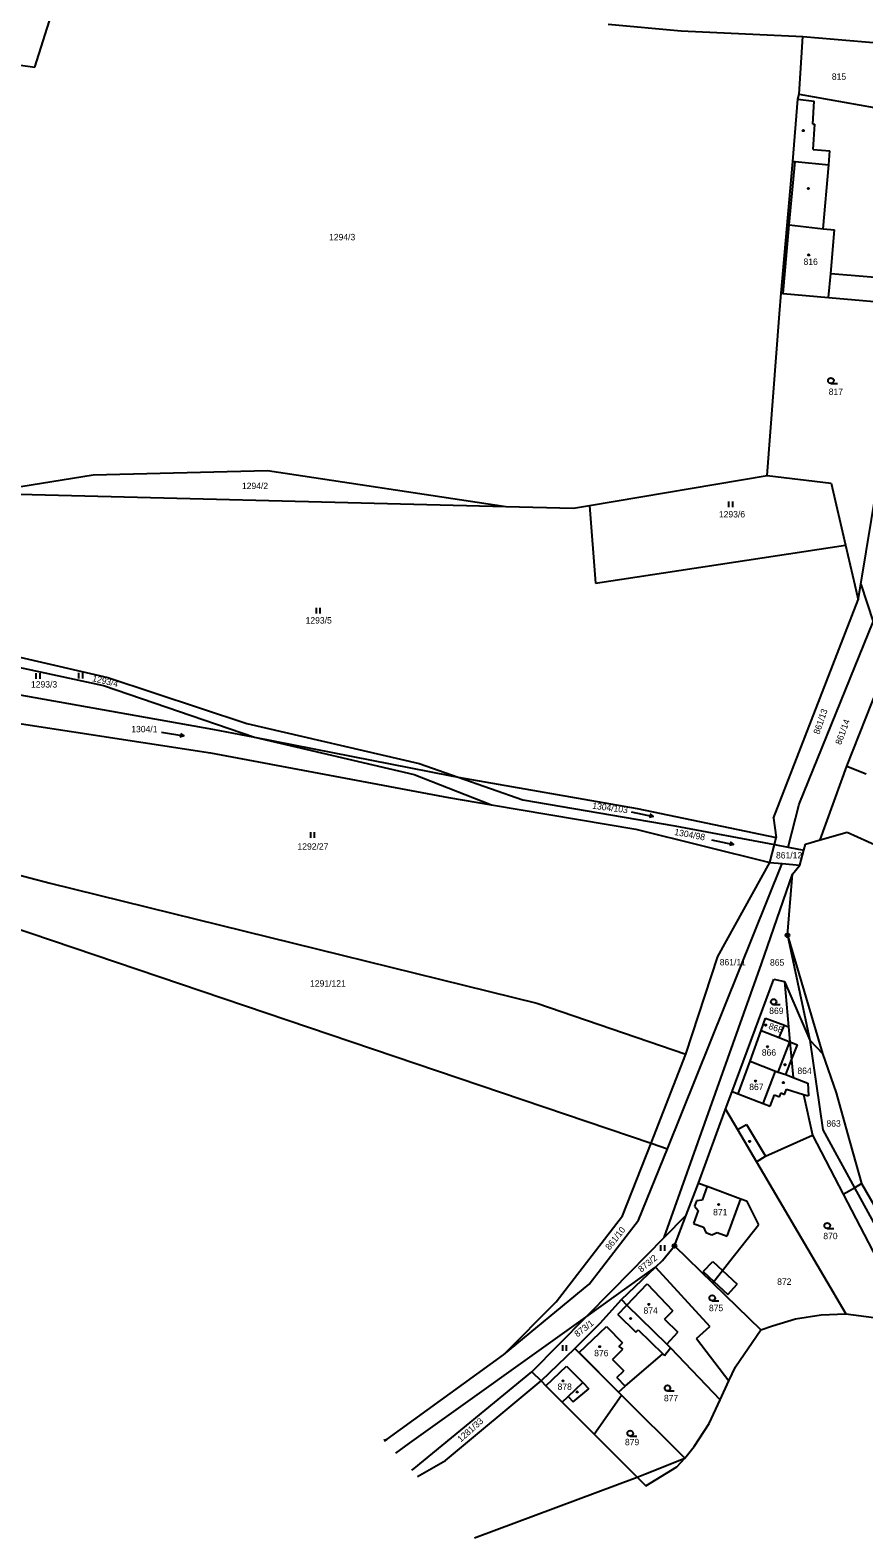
# Model space of a CAD drawing. Extents: x -779596 to -776743, y -1030330 to -1024513.
# Drawn here: x -778014.2 to -777792.7, y -1025697.8 to -1025297.1 of the extents above; entities that cross this region are included whole.
import ezdxf

# ---------------------------------------------------------------- set-up
doc = ezdxf.new("R2010")
doc.units = 0
for name, color, linetype in [('hranice parcel', 7, 'Continuous'), ('hranice vnitřní', 7, 'Continuous'), ('kultura', 7, 'Continuous'), ('Kód', 7, 'Continuous'), ('č_pacel stav_', 7, 'Continuous'), ('č_parcel poz_', 7, 'Continuous')]:
    doc.layers.add(name, color=color, linetype=linetype)

msp = doc.modelspace()

# ---------------------------------------------------------------- linework, layer by layer
at = {"layer": 'hranice parcel'}
for points in [[(-778012.95, -1025306.97), (-778004.12, -1025278.91)], [(-777860.63, -1025295.52), (-777841.25, -1025297.36)], [(-777841.25, -1025297.36), (-777808.98, -1025298.81)], [(-777809.95, -1025314.14), (-777808.98, -1025298.81)], [(-777808.98, -1025298.81), (-777788.09, -1025300.64)], [(-778028.28, -1025304.88), (-778012.95, -1025306.97)], [(-777811.57, -1025332.03), (-777810.25, -1025315.48)], [(-777810.25, -1025315.48), (-777809.95, -1025314.14)], [(-777809.95, -1025314.14), (-777789.98, -1025317.73)], [(-777814.67, -1025367.05), (-777811.57, -1025332.03)], [(-777815.16, -1025372.54), (-777814.67, -1025367.05)], [(-777814.67, -1025367.05), (-777814.17, -1025367.09)], [(-777814.17, -1025367.09), (-777802.12, -1025368.16)], [(-777802.12, -1025368.16), (-777781.81, -1025369.97)], [(-777818.4, -1025415.44), (-777815.16, -1025372.54)], [(-778027.77, -1025420.18), (-777997.46, -1025415.31)], [(-777997.46, -1025415.31), (-777951.14, -1025414.16)], [(-777951.14, -1025414.16), (-777887.84, -1025423.69)], [(-777865.62, -1025423.43), (-777818.4, -1025415.44)], [(-777818.4, -1025415.44), (-777801.44, -1025417.56)], [(-778027.77, -1025420.18), (-777887.84, -1025423.69)], [(-777801.44, -1025417.56), (-777797.59, -1025434.03)], [(-777793.53, -1025444.4), (-777789.28, -1025418.59)], [(-777887.84, -1025423.69), (-777869.84, -1025424.14)], [(-777869.84, -1025424.14), (-777865.62, -1025423.43)], [(-777865.62, -1025423.43), (-777864.07, -1025444.05)], [(-777864.07, -1025444.05), (-777797.59, -1025434.03)], [(-777797.59, -1025434.03), (-777795.13, -1025444.58)], [(-777795.13, -1025444.58), (-777794.21, -1025448.52)], [(-777794.21, -1025448.52), (-777793.53, -1025444.4)], [(-777793.53, -1025444.4), (-777790.21, -1025454.41)], [(-777816.77, -1025506.5), (-777794.21, -1025448.52)], [(-777809.88, -1025502.83), (-777790.21, -1025454.41)], [(-778040.44, -1025458.35), (-777993.61, -1025469.18)], [(-778040.76, -1025461.34), (-777994.79, -1025471.25)], [(-777993.61, -1025469.18), (-777956.63, -1025481.4)], [(-778039.94, -1025469.72), (-777965.75, -1025482.86)], [(-777994.79, -1025471.25), (-777954.64, -1025485.05)], [(-777797.26, -1025492.75), (-777788.88, -1025471.44)], [(-778039.13, -1025478.05), (-777966.3, -1025489.21)], [(-777965.75, -1025482.86), (-777954.64, -1025485.05)], [(-777956.63, -1025481.4), (-777910.87, -1025492.03)], [(-777954.64, -1025485.05), (-777902.85, -1025495.24)], [(-777954.64, -1025485.05), (-777912.18, -1025494.91)], [(-777966.3, -1025489.21), (-777903.1, -1025501.05)], [(-777910.87, -1025492.03), (-777900.51, -1025495.65)], [(-777804.37, -1025512.26), (-777797.26, -1025492.75)], [(-777797.26, -1025492.75), (-777792.15, -1025494.76)], [(-777912.18, -1025494.91), (-777891.67, -1025502.98)], [(-777902.85, -1025495.24), (-777900.51, -1025495.65)], [(-777900.51, -1025495.65), (-777852.96, -1025504)], [(-777900.51, -1025495.65), (-777883.35, -1025501.65)], [(-777903.1, -1025501.05), (-777891.67, -1025502.98)], [(-777891.67, -1025502.98), (-777853.31, -1025509.46)], [(-777883.35, -1025501.65), (-777842.95, -1025508.56)], [(-777852.96, -1025504), (-777816.01, -1025511.63)], [(-777812.86, -1025514.21), (-777809.88, -1025502.83)], [(-777842.95, -1025508.56), (-777816.48, -1025513.53)], [(-777816.77, -1025506.5), (-777816.01, -1025511.63)], [(-777853.31, -1025509.46), (-777817.68, -1025518.32)], [(-777816.48, -1025513.53), (-777816.01, -1025511.63)], [(-777808.25, -1025513.45), (-777804.37, -1025512.26)], [(-777804.37, -1025512.26), (-777797.12, -1025510.29)], [(-777797.12, -1025510.29), (-777788.92, -1025513.97)], [(-778036.06, -1025516.7), (-778008.92, -1025523.8)], [(-777817.68, -1025518.32), (-777816.48, -1025513.53)], [(-777816.48, -1025513.53), (-777812.86, -1025514.21)], [(-777812.86, -1025514.21), (-777808.67, -1025515)], [(-777809.76, -1025519.05), (-777808.67, -1025515)], [(-777808.67, -1025515), (-777808.25, -1025513.45)], [(-777844.94, -1025594.37), (-777814.43, -1025518.62)], [(-777831.51, -1025543.32), (-777817.68, -1025518.32)], [(-777817.68, -1025518.32), (-777814.43, -1025518.62)], [(-777814.43, -1025518.62), (-777809.76, -1025519.05)], [(-777811.66, -1025521.39), (-777809.76, -1025519.05)], [(-778008.92, -1025523.8), (-777879.61, -1025555.7)], [(-777819.94, -1025545.22), (-777811.66, -1025521.39)], [(-777813.02, -1025537.66), (-777811.66, -1025521.39)], [(-778036.95, -1025529.43), (-777849.27, -1025592.9)], [(-777813.02, -1025537.66), (-777807.04, -1025565.5)], [(-777845.75, -1025617.95), (-777819.94, -1025545.22)], [(-777840.02, -1025569.28), (-777831.51, -1025543.32)], [(-777827.76, -1025579.16), (-777816.65, -1025549.3)], [(-777816.65, -1025549.3), (-777813.78, -1025549.91)], [(-777813.78, -1025549.91), (-777807.04, -1025565.5)], [(-777813.78, -1025549.91), (-777812.71, -1025561.94)], [(-777879.61, -1025555.7), (-777840.02, -1025569.28)], [(-777820.05, -1025562.97), (-777818.87, -1025559.71)], [(-777818.87, -1025559.71), (-777813.85, -1025561.52)], [(-777822.97, -1025571.07), (-777820.05, -1025562.97)], [(-777820.05, -1025562.97), (-777815.2, -1025564.86)], [(-777815.2, -1025564.86), (-777812.35, -1025565.97)], [(-777813.85, -1025561.52), (-777812.71, -1025561.94)], [(-777812.71, -1025561.94), (-777812.35, -1025565.97)], [(-777849.27, -1025592.9), (-777840.02, -1025569.28)], [(-777812.35, -1025565.97), (-777811.93, -1025570.74)], [(-777807.04, -1025565.5), (-777803.7, -1025569.05)], [(-777807.04, -1025565.5), (-777803.66, -1025589.38)], [(-777803.7, -1025569.05), (-777800.12, -1025579.56)], [(-777826.12, -1025579.79), (-777822.97, -1025571.07)], [(-777822.97, -1025571.07), (-777816.17, -1025573.72)], [(-777811.93, -1025570.74), (-777811.51, -1025575.46)], [(-777816.17, -1025573.72), (-777815.45, -1025574)], [(-777815.45, -1025574), (-777813.49, -1025574.69)], [(-777813.49, -1025574.69), (-777811.51, -1025575.46)], [(-777811.51, -1025575.46), (-777807.59, -1025576.98)], [(-777807.59, -1025576.98), (-777807.46, -1025580.31)], [(-777829.5, -1025583.86), (-777827.76, -1025579.16)], [(-777827.76, -1025579.16), (-777826.12, -1025579.79)], [(-777808.73, -1025579.93), (-777806.33, -1025590.77)], [(-777808.73, -1025579.93), (-777807.46, -1025580.31)], [(-777800.12, -1025579.56), (-777797.15, -1025590.05)], [(-777836.67, -1025603.51), (-777829.5, -1025583.86)], [(-777829.5, -1025583.86), (-777826.29, -1025589.3)], [(-777826.29, -1025589.3), (-777821.28, -1025597.82)], [(-777803.66, -1025589.38), (-777795.23, -1025604.74)], [(-777856.84, -1025612.23), (-777849.27, -1025592.9)], [(-777849.27, -1025592.9), (-777844.94, -1025594.37)], [(-777818.82, -1025596.37), (-777806.33, -1025590.77)], [(-777806.33, -1025590.77), (-777798.19, -1025606.43)], [(-777797.15, -1025590.05), (-777793.31, -1025603.64)], [(-777852.58, -1025613.33), (-777844.94, -1025594.37)], [(-777821.28, -1025597.82), (-777818.82, -1025596.37)], [(-777821.28, -1025597.82), (-777797.48, -1025638.2)], [(-777839.92, -1025612.03), (-777836.67, -1025603.51)], [(-777836.67, -1025603.51), (-777834.38, -1025604.35)], [(-777834.38, -1025604.35), (-777825.39, -1025607.66)], [(-777798.19, -1025606.43), (-777795.23, -1025604.74)], [(-777795.23, -1025604.74), (-777793.31, -1025603.64)], [(-777795.23, -1025604.74), (-777774.45, -1025642.57)], [(-777825.39, -1025607.66), (-777823.91, -1025608.21)], [(-777823.91, -1025608.21), (-777820.74, -1025614.57)], [(-777798.19, -1025606.43), (-777780.25, -1025640.96)], [(-777874.49, -1025635.07), (-777856.84, -1025612.23)], [(-777865.73, -1025630.39), (-777852.58, -1025613.33)], [(-777845.75, -1025617.95), (-777839.92, -1025612.03)], [(-777843.03, -1025620.17), (-777839.92, -1025612.03)], [(-777828.4, -1025624.36), (-777820.74, -1025614.57)], [(-777859.53, -1025631.94), (-777845.75, -1025617.95)], [(-777846.2, -1025624.06), (-777843.03, -1025620.17)], [(-777843.03, -1025620.17), (-777832.86, -1025630.06)], [(-777848.08, -1025625.84), (-777846.2, -1025624.06)], [(-777830.27, -1025626.75), (-777828.4, -1025624.36)], [(-777866.63, -1025639.13), (-777848.08, -1025625.84)], [(-777857.13, -1025634.46), (-777848.08, -1025625.84)], [(-777848.08, -1025625.84), (-777833.69, -1025641.63)], [(-777832.56, -1025629.67), (-777830.27, -1025626.75)], [(-777888.44, -1025649.11), (-777865.73, -1025630.39)], [(-777866.63, -1025639.13), (-777859.53, -1025631.94)], [(-777832.86, -1025630.06), (-777832.56, -1025629.67)], [(-777832.86, -1025630.06), (-777820.1, -1025642.48)], [(-777888.44, -1025649.11), (-777874.49, -1025635.07)], [(-777862.77, -1025640.73), (-777857.13, -1025634.46)], [(-777857.13, -1025634.46), (-777855.71, -1025635.95)], [(-777855.71, -1025635.95), (-777845.05, -1025646.28)], [(-777913.42, -1025672.65), (-777866.63, -1025639.13)], [(-777880.94, -1025653.62), (-777866.63, -1025639.13)], [(-777869.52, -1025647.43), (-777862.77, -1025640.73)], [(-777820.1, -1025642.48), (-777817.01, -1025641.46)], [(-777817.01, -1025641.46), (-777810.86, -1025639.6)], [(-777810.86, -1025639.6), (-777804.07, -1025638.49)], [(-777804.07, -1025638.49), (-777797.48, -1025638.2)], [(-777797.48, -1025638.2), (-777784.69, -1025639.9)], [(-777837.17, -1025644.81), (-777833.69, -1025641.63)], [(-777837.17, -1025644.81), (-777828.56, -1025656.06)], [(-777826.82, -1025652.37), (-777820.1, -1025642.48)], [(-777919.4, -1025671.56), (-777888.44, -1025649.11)], [(-777878.47, -1025656.09), (-777869.52, -1025647.43)], [(-777869.52, -1025647.43), (-777857.92, -1025659.08)], [(-777856.12, -1025657.42), (-777846.1, -1025648.85)], [(-777846.1, -1025648.85), (-777845.66, -1025649.29)], [(-777845.66, -1025649.29), (-777844.06, -1025647.24)], [(-777845.05, -1025646.28), (-777844.06, -1025647.24)], [(-777844.06, -1025647.24), (-777830.91, -1025661.06)], [(-777828.56, -1025656.06), (-777826.82, -1025652.37)], [(-777912.2, -1025679.36), (-777880.94, -1025653.62)], [(-777903.92, -1025677.2), (-777878.47, -1025656.09)], [(-777880.94, -1025653.62), (-777878.47, -1025656.09)], [(-777878.47, -1025656.09), (-777877.2, -1025657.36)], [(-777877.2, -1025657.36), (-777872.87, -1025661.7)], [(-777857.92, -1025659.08), (-777856.12, -1025657.42)], [(-777830.91, -1025661.06), (-777828.56, -1025656.06)], [(-777864.4, -1025670.18), (-777857.15, -1025659.86)], [(-777857.92, -1025659.08), (-777857.15, -1025659.86)], [(-777857.15, -1025659.86), (-777840.33, -1025676.57)], [(-777833.85, -1025667.34), (-777830.91, -1025661.06)], [(-777872.87, -1025661.7), (-777864.4, -1025670.18)], [(-777837.81, -1025673.47), (-777833.85, -1025667.34)], [(-777920.285, -1025671.798), (-777919.4, -1025671.56)], [(-777920.215, -1025671.873), (-777919.4, -1025671.56)], [(-777920.078, -1025672.021), (-777919.4, -1025671.56)], [(-777917.07, -1025675.262), (-777913.42, -1025672.65)], [(-777864.4, -1025670.18), (-777852.95, -1025681.65)], [(-777840.33, -1025676.57), (-777837.81, -1025673.47)], [(-777911.333, -1025681.444), (-777903.92, -1025677.2)], [(-777850.78, -1025680.78), (-777840.33, -1025676.57)], [(-777912.85, -1025679.81), (-777912.2, -1025679.36)], [(-777852.95, -1025681.65), (-777850.78, -1025680.78)], [(-777896.184, -1025697.768), (-777852.95, -1025681.65)]]:
    msp.add_lwpolyline(points, dxfattribs=at)
at = {"layer": 'hranice vnitřní'}
for points in [[(-777810.25, -1025315.48), (-777805.9, -1025316.06)], [(-777806.32, -1025322.11), (-777805.9, -1025316.06)], [(-777806.32, -1025322.11), (-777805.72, -1025322.16)], [(-777806.19, -1025328.86), (-777805.72, -1025322.16)], [(-777806.19, -1025328.86), (-777801.79, -1025329.24)], [(-777812.53, -1025348.9), (-777811.01, -1025332.08)], [(-777811.57, -1025332.03), (-777811.01, -1025332.08)], [(-777811.01, -1025332.08), (-777802.03, -1025332.89)], [(-777803.56, -1025349.92), (-777802.03, -1025332.89)], [(-777802.03, -1025332.89), (-777801.79, -1025329.24)], [(-777814.17, -1025367.09), (-777812.53, -1025348.9)], [(-777812.53, -1025348.9), (-777803.56, -1025349.92)], [(-777803.56, -1025349.92), (-777800.5, -1025350.21)], [(-777801.54, -1025361.81), (-777800.5, -1025350.21)], [(-777802.12, -1025368.16), (-777801.54, -1025361.81)], [(-777801.54, -1025361.81), (-777781.15, -1025363.46)], [(-777813.02, -1025537.66), (-777803.7, -1025569.05)], [(-777815.2, -1025564.86), (-777813.85, -1025561.52)], [(-777815.45, -1025574), (-777812.35, -1025565.97)], [(-777812.35, -1025565.97), (-777810.35, -1025566.75)], [(-777811.93, -1025570.74), (-777810.35, -1025566.75)], [(-777813.49, -1025574.69), (-777811.93, -1025570.74)], [(-777819.48, -1025582.32), (-777816.17, -1025573.72)], [(-777826.12, -1025579.79), (-777819.48, -1025582.32)], [(-777817.59, -1025583.04), (-777816.45, -1025580.04)], [(-777816.45, -1025580.04), (-777815.12, -1025580.55)], [(-777815.12, -1025580.55), (-777814.74, -1025579.56)], [(-777814.74, -1025579.56), (-777813.79, -1025579.93)], [(-777813.79, -1025579.93), (-777813.27, -1025578.58)], [(-777813.27, -1025578.58), (-777808.73, -1025579.93)], [(-777819.48, -1025582.32), (-777817.59, -1025583.04)], [(-777826.29, -1025589.3), (-777823.91, -1025587.97)], [(-777823.91, -1025587.97), (-777818.82, -1025596.37)], [(-777834.38, -1025604.35), (-777835.71, -1025608)], [(-777793.31, -1025603.64), (-777769.99, -1025644.12)], [(-777837.15, -1025608.24), (-777837.69, -1025609.67)], [(-777835.71, -1025608), (-777837.15, -1025608.24)], [(-777829.02, -1025617.6), (-777825.39, -1025607.66)], [(-777836.79, -1025610.81), (-777838.03, -1025614.23)], [(-777837.69, -1025609.67), (-777836.79, -1025610.81)], [(-777838.03, -1025614.23), (-777835.34, -1025615.24)], [(-777835.34, -1025615.24), (-777834.68, -1025616.65)], [(-777834.68, -1025616.65), (-777833.13, -1025617.23)], [(-777833.13, -1025617.23), (-777831.72, -1025616.59)], [(-777831.72, -1025616.59), (-777829.02, -1025617.6)], [(-777835.38, -1025627.03), (-777832.85, -1025624.33)], [(-777832.85, -1025624.33), (-777830.27, -1025626.75)], [(-777835.38, -1025627.03), (-777832.56, -1025629.67)], [(-777830.27, -1025626.75), (-777826.36, -1025630.4)], [(-777855.71, -1025635.95), (-777850.32, -1025630.26)], [(-777850.32, -1025630.26), (-777843.51, -1025637.41)], [(-777832.56, -1025629.67), (-777828.89, -1025633.1)], [(-777828.89, -1025633.1), (-777826.36, -1025630.4)], [(-777858.11, -1025638.41), (-777855.71, -1025635.95)], [(-777845.69, -1025639.68), (-777843.51, -1025637.41)], [(-777858.11, -1025638.41), (-777853.32, -1025643.11)], [(-777845.69, -1025639.68), (-777842.11, -1025643.15)], [(-777868.35, -1025648.54), (-777861.12, -1025641.62)], [(-777861.12, -1025641.62), (-777856.81, -1025645.91)], [(-777853.32, -1025643.11), (-777852.69, -1025642.47)], [(-777852.69, -1025642.47), (-777846.1, -1025648.85)], [(-777845.05, -1025646.28), (-777842.11, -1025643.15)], [(-777868.35, -1025648.54), (-777857.92, -1025659.08)], [(-777859.52, -1025650.36), (-777856.73, -1025647.59)], [(-777857.81, -1025646.91), (-777856.81, -1025645.91)], [(-777857.81, -1025646.91), (-777856.73, -1025647.59)], [(-777877.2, -1025657.36), (-777871.69, -1025652.11)], [(-777871.69, -1025652.11), (-777867.4, -1025656.49)], [(-777859.52, -1025650.36), (-777856.54, -1025653.37)], [(-777858.38, -1025655.14), (-777856.54, -1025653.37)], [(-777871.3, -1025660.2), (-777867.4, -1025656.49)], [(-777867.4, -1025656.49), (-777865.79, -1025658.18)], [(-777858.38, -1025655.14), (-777856.12, -1025657.42)], [(-777872.87, -1025661.7), (-777871.3, -1025660.2)], [(-777871.3, -1025660.2), (-777869.92, -1025661.62)], [(-777869.92, -1025661.62), (-777865.79, -1025658.18)], [(-777842.44, -1025678.89), (-777840.33, -1025676.57)], [(-777850.66, -1025683.94), (-777842.44, -1025678.89)], [(-777852.95, -1025681.65), (-777850.66, -1025683.94)]]:
    msp.add_lwpolyline(points, dxfattribs=at)
at = {"layer": 'kultura'}
for points in [[(-777801.49, -1025391.03), (-777799.74, -1025391.03)], [(-777828.617, -1025423.915), (-777828.617, -1025422.415)], [(-777827.583, -1025423.915), (-777827.583, -1025422.415)], [(-777938.177, -1025452.155), (-777938.177, -1025450.655)], [(-777937.143, -1025452.155), (-777937.143, -1025450.655)], [(-778012.627, -1025469.475), (-778012.627, -1025467.975)], [(-778011.593, -1025469.475), (-778011.593, -1025467.975)], [(-778001.267, -1025469.455), (-778001.267, -1025467.955)], [(-778000.233, -1025469.455), (-778000.233, -1025467.955)], [(-777979.345, -1025483.655), (-777973.435, -1025484.685)], [(-777974.334, -1025484.022), (-777973.435, -1025484.685), (-777974.506, -1025485.006)], [(-777854.588, -1025504.887), (-777848.712, -1025506.093)], [(-777849.591, -1025505.403), (-777848.712, -1025506.093), (-777849.792, -1025506.381)], [(-777939.687, -1025511.755), (-777939.687, -1025510.255)], [(-777938.653, -1025511.755), (-777938.653, -1025510.255)], [(-777833.208, -1025512.297), (-777827.332, -1025513.503)], [(-777828.211, -1025512.813), (-777827.332, -1025513.503), (-777828.412, -1025513.791)], [(-777816.69, -1025556.09), (-777814.94, -1025556.09)], [(-777802.46, -1025615.56), (-777800.71, -1025615.56)], [(-777846.677, -1025621.535), (-777846.677, -1025620.035)], [(-777845.643, -1025621.535), (-777845.643, -1025620.035)], [(-777833.02, -1025634.8), (-777831.27, -1025634.8)], [(-777872.747, -1025648.105), (-777872.747, -1025646.605)], [(-777871.713, -1025648.105), (-777871.713, -1025646.605)], [(-777844.9, -1025658.73), (-777843.15, -1025658.73)], [(-777854.8, -1025670.75), (-777853.05, -1025670.75)]]:
    msp.add_lwpolyline(points, dxfattribs=at)
for centre, radius in [((-777808.82, -1025323.84), 0.175), ((-777807.5, -1025339.22), 0.175), ((-777807.36, -1025356.87), 0.175), ((-777801.49, -1025390.28), 0.75), ((-777816.69, -1025555.34), 0.75), ((-777818.84, -1025561.53), 0.175), ((-777818.32, -1025567.26), 0.175), ((-777813.7, -1025572.04), 0.175), ((-777821.52, -1025576.38), 0.175), ((-777814.11, -1025576.81), 0.175), ((-777823.09, -1025592.41), 0.175), ((-777831.29, -1025609.19), 0.175), ((-777802.46, -1025614.81), 0.75), ((-777833.02, -1025634.05), 0.75), ((-777849.86, -1025635.73), 0.175), ((-777854.68, -1025639.48), 0.175), ((-777862.91, -1025646.97), 0.175), ((-777872.64, -1025656.05), 0.175), ((-777844.9, -1025657.98), 0.75), ((-777868.9, -1025658.99), 0.175), ((-777854.8, -1025670), 0.75)]:
    msp.add_circle(centre, radius, dxfattribs=at)
at = {"layer": 'Kód'}
for centre, radius in [((-777813.02, -1025537.66), 0.5), ((-777813.02, -1025537.66), 0.032), ((-777843.03, -1025620.17), 0.5), ((-777843.03, -1025620.17), 0.032)]:
    msp.add_circle(centre, radius, dxfattribs=at)

# ---------------------------------------------------------------- texts
at = {"layer": 'č_pacel stav_'}
for s, p in [('816', (-777808.76, -1025359.53)), ('866', (-777819.84, -1025569.64)), ('867', (-777823.18, -1025578.79)), ('871', (-777832.78, -1025612.06)), ('874', (-777851.27, -1025638.21)), ('876', (-777864.38, -1025649.52)), ('878', (-777874.11, -1025658.46))]:
    msp.add_text(s, height=1.7, dxfattribs=at).set_placement(p)
msp.add_text('868', height=1.7, rotation=340.60271, dxfattribs=at).set_placement((-777818.205, -1025562.458))
at = {"layer": 'č_parcel poz_'}
for s, p in [('815', (-777801.23, -1025310.34)), ('1294/3', (-777934.82, -1025352.98)), ('817', (-777802.07, -1025394.08)), ('1294/2', (-777957.97, -1025419.09)), ('1293/6', (-777831.24, -1025426.63)), ('1293/5', (-777941.05, -1025454.82)), ('1293/3', (-778014.01, -1025471.83)), ('1304/1', (-777987.37, -1025483.72)), ('1292/27', (-777943.21, -1025514.91)), ('861/12', (-777816.07, -1025517.25)), ('861/11', (-777831.02, -1025545.66)), ('865', (-777817.67, -1025545.72)), ('1291/121', (-777939.86, -1025551.3)), ('869', (-777817.87, -1025558.56)), ('864', (-777810.38, -1025574.5)), ('863', (-777802.66, -1025588.51)), ('870', (-777803.5, -1025618.41)), ('872', (-777815.76, -1025630.54)), ('875', (-777833.89, -1025637.54)), ('877', (-777845.84, -1025661.48)), ('879', (-777856.2, -1025673.16))]:
    msp.add_text(s, height=1.7, dxfattribs=at).set_placement(p)
for s, rotation, p in [('1293/4', 346.70276, (-777997.85, -1025470.112)), ('861/13', 71.00056, (-777804.583, -1025484.416)), ('861/14', 69.80056, (-777798.808, -1025487.174)), ('1304/103', 352.5028, (-777864.956, -1025504.008)), ('1304/98', 349.60278, (-777843.168, -1025510.99)), ('861/10', 51.90041, (-777860.253, -1025621.43)), ('873/2', 39.60031, (-777851.834, -1025627.319)), ('873/1', 37.6003, (-777868.834, -1025644.53)), ('1281/33', 41.60033, (-777899.804, -1025672.448))]:
    msp.add_text(s, height=1.7, rotation=rotation, dxfattribs=at).set_placement(p)

doc.saveas('drawing.dxf')
